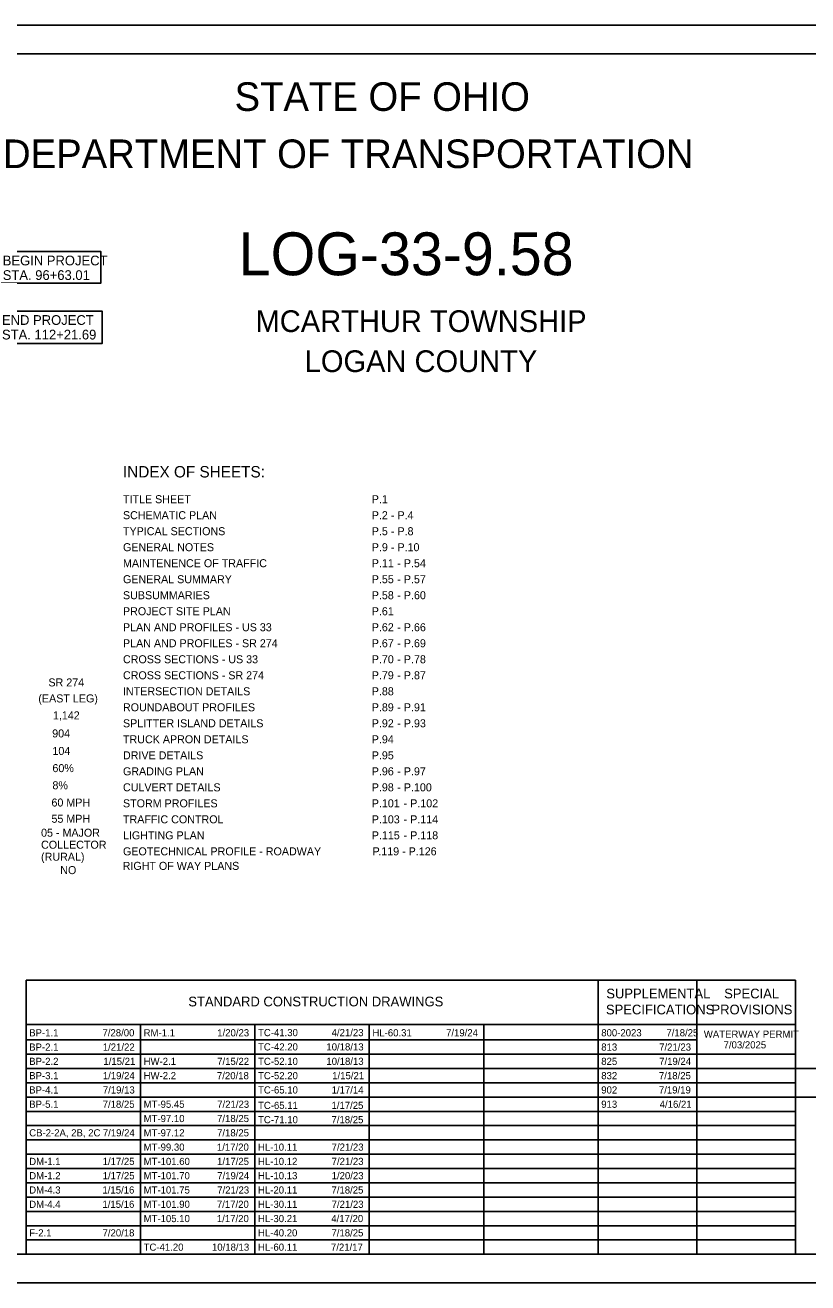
# Model space of a CAD drawing. Extents: x -5.9 to 34, y 0 to 22.
# Drawn here: x 10.13 to 23.82, y 0 to 22 of the extents above; entities that cross this region are included whole.
import ezdxf

# ---------------------------------------------------------------- set-up
doc = ezdxf.new("R2010")
doc.units = 0
for name, color, linetype in [('SH_Border', 7, 'Continuous'), ('SH_Cut_Line', 7, 'Continuous'), ('SH_Data', 7, 'Continuous'), ('SH_Text', 7, 'Continuous')]:
    doc.layers.add(name, color=color, linetype=linetype)

msp = doc.modelspace()

# ---------------------------------------------------------------- linework, layer by layer
at = {"layer": 'SH_Border'}
msp.add_lwpolyline([(1.5, 21.5), (33.5, 21.5), (33.5, 0.5), (1.5, 0.5)], close=True, dxfattribs=at)
at = {"layer": 'SH_Cut_Line'}
msp.add_lwpolyline([(0, 0), (34, 0), (34, 22), (0, 22)], close=True, dxfattribs=at)
at = {"layer": 'SH_Data'}
for p, q in [((10.15, 5.292), (23.6, 5.292)), ((10.15, 0.5), (10.15, 5.292)), ((20.15, 0.5), (20.15, 5.292)), ((21.875, 0.5), (21.875, 5.292)), ((23.6, 0.5), (23.6, 5.292)), ((10.15, 4.521), (23.6, 4.521)), ((12.15, 0.5), (12.15, 4.521)), ((14.15, 0.5), (14.15, 4.521)), ((16.15, 0.5), (16.15, 4.521)), ((18.15, 0.5), (18.15, 4.521)), ((10.15, 4.25), (21.875, 4.25)), ((10.15, 4), (23.6, 4)), ((10.15, 3.75), (23.6, 3.75)), ((23.6, 3.75), (26.4, 3.75)), ((23.6, 0.5), (23.6, 3.75)), ((10.15, 3.5), (23.6, 3.5)), ((10.15, 3.25), (23.6, 3.25)), ((23.6, 3.25), (26.4, 3.25)), ((10.15, 3), (23.6, 3)), ((10.15, 2.75), (23.6, 2.75)), ((10.15, 2.5), (23.6, 2.5)), ((10.15, 2.25), (23.6, 2.25)), ((10.15, 2), (23.6, 2)), ((10.15, 1.75), (23.6, 1.75)), ((10.15, 1.5), (23.6, 1.5)), ((10.15, 1.25), (23.6, 1.25)), ((10.15, 1), (23.6, 1)), ((10.15, 0.75), (23.6, 0.75))]:
    msp.add_line(p, q, dxfattribs=at)
at = {"layer": 'SH_Text'}
for points in [[(9.672, 17.488), (11.459, 17.488), (11.459, 18.038), (9.672, 18.038)], [(9.659, 16.431), (11.478, 16.431), (11.478, 16.997), (9.659, 16.997)]]:
    msp.add_lwpolyline(points, close=True, dxfattribs=at)

# ---------------------------------------------------------------- texts
for s, height, p in [('STATE OF OHIO', 0.5, (13.795, 20.5)), ('DEPARTMENT OF TRANSPORTATION', 0.5, (9.747, 19.5)), ('LOG-33-9.58', 0.75, (13.868, 17.625)), ('BEGIN PROJECT', 0.17, (9.742, 17.798)), ('STA. 96+63.01', 0.17, (9.742, 17.543)), ('MCARTHUR TOWNSHIP', 0.38, (14.162, 16.632)), ('END PROJECT', 0.17, (9.729, 16.757)), ('STA. 112+21.69', 0.17, (9.729, 16.502)), ('LOGAN COUNTY', 0.38, (15.021, 15.932)), ('INDEX OF SHEETS:', 0.2, (11.844, 14.088)), ('TITLE SHEET', 0.14, (11.844, 13.638)), ('P.1', 0.14, (16.193, 13.638)), ('SCHEMATIC PLAN', 0.14, (11.844, 13.358)), ('P.2', 0.14, (16.193, 13.358)), ('P.4', 0.14, (16.642, 13.358)), ('TYPICAL SECTIONS', 0.14, (11.844, 13.078)), ('P.5', 0.14, (16.193, 13.078)), (' - ', 0.14, (16.475, 13.358)), ('P.8', 0.14, (16.642, 13.078)), (' - ', 0.14, (16.475, 13.078)), ('GENERAL NOTES', 0.14, (11.844, 12.798)), ('P.9', 0.14, (16.193, 12.798)), (' - ', 0.14, (16.475, 12.798)), ('P.10', 0.14, (16.642, 12.798)), ('MAINTENENCE OF TRAFFIC', 0.14, (11.844, 12.518)), ('P.11', 0.14, (16.193, 12.518)), (' - ', 0.14, (16.586, 12.518)), ('P.54', 0.14, (16.754, 12.518)), ('GENERAL SUMMARY', 0.14, (11.844, 12.238)), ('P.55', 0.14, (16.193, 12.238)), ('P.57', 0.14, (16.754, 12.238)), (' - ', 0.14, (16.586, 12.238)), ('SUBSUMMARIES', 0.14, (11.844, 11.958)), ('P.58', 0.14, (16.193, 11.958)), (' - ', 0.14, (16.586, 11.958)), ('P.60', 0.14, (16.754, 11.958)), ('PROJECT SITE PLAN', 0.14, (11.844, 11.678)), ('P.61', 0.14, (16.193, 11.678)), ('PLAN AND PROFILES - US 33', 0.14, (11.844, 11.398)), ('P.62', 0.14, (16.193, 11.398)), (' - ', 0.14, (16.586, 11.398)), ('P.66', 0.14, (16.754, 11.398)), ('PLAN AND PROFILES - SR 274', 0.14, (11.844, 11.118)), ('P.67', 0.14, (16.193, 11.118)), ('P.69', 0.14, (16.754, 11.118)), (' - ', 0.14, (16.586, 11.118)), ('CROSS SECTIONS - US 33', 0.14, (11.844, 10.838)), ('P.70', 0.14, (16.193, 10.838)), (' - ', 0.14, (16.586, 10.838)), ('P.78', 0.14, (16.754, 10.838)), ('SR 274', 0.14, (10.541, 10.433)), ('CROSS SECTIONS - SR 274', 0.14, (11.844, 10.558)), ('P.79', 0.14, (16.193, 10.558)), (' - ', 0.14, (16.586, 10.558)), ('P.87', 0.14, (16.754, 10.558)), ('INTERSECTION DETAILS', 0.14, (11.844, 10.278)), ('P.88', 0.14, (16.193, 10.278)), ('(EAST LEG)', 0.14, (10.365, 10.153)), ('ROUNDABOUT PROFILES', 0.14, (11.844, 9.998)), ('P.89', 0.14, (16.193, 9.998)), ('P.91', 0.14, (16.754, 9.998)), ('1,142', 0.14, (10.619, 9.856)), (' - ', 0.14, (16.586, 9.998)), ('904', 0.14, (10.607, 9.541)), ('SPLITTER ISLAND DETAILS ', 0.14, (11.844, 9.718)), ('P.92', 0.14, (16.193, 9.718)), (' - ', 0.14, (16.586, 9.718)), ('P.93', 0.14, (16.754, 9.718)), ('TRUCK APRON DETAILS', 0.14, (11.844, 9.438)), ('P.94', 0.14, (16.193, 9.438)), ('104', 0.14, (10.611, 9.234)), ('DRIVE DETAILS', 0.14, (11.844, 9.158)), ('P.95', 0.14, (16.193, 9.158)), ('60%', 0.14, (10.611, 8.934)), ('GRADING PLAN', 0.14, (11.844, 8.878)), ('P.96', 0.14, (16.193, 8.878)), (' - ', 0.14, (16.586, 8.878)), ('P.97', 0.14, (16.754, 8.878)), ('8%', 0.14, (10.611, 8.634)), ('CULVERT DETAILS', 0.14, (11.844, 8.598)), ('P.98', 0.14, (16.193, 8.598)), (' - ', 0.14, (16.586, 8.598)), ('P.100', 0.14, (16.754, 8.598)), ('60 MPH', 0.14, (10.594, 8.332)), ('STORM PROFILES', 0.14, (11.844, 8.318)), ('P.101', 0.14, (16.193, 8.318)), (' - ', 0.14, (16.698, 8.318)), ('P.102', 0.14, (16.865, 8.318)), ('55 MPH', 0.14, (10.594, 8.048)), ('TRAFFIC CONTROL', 0.14, (11.844, 8.038)), ('P.103', 0.14, (16.193, 8.038)), ('P.114', 0.14, (16.865, 8.038)), ('05 - MAJOR ', 0.14, (10.412, 7.804)), (' - ', 0.14, (16.698, 8.038)), ('COLLECTOR ', 0.14, (10.412, 7.594)), ('LIGHTING PLAN', 0.14, (11.844, 7.758)), ('P.115', 0.14, (16.193, 7.758)), (' - ', 0.14, (16.698, 7.758)), ('P.118', 0.14, (16.865, 7.758)), ('(RURAL)', 0.14, (10.412, 7.384)), ('GEOTECHNICAL PROFILE - ROADWAY', 0.14, (11.844, 7.478)), ('       P', 0.14, (15.844, 7.478)), ('.119 - P.126', 0.14, (16.307, 7.478)), ('NO', 0.14, (10.748, 7.15)), ('RIGHT OF WAY PLANS', 0.14, (11.838, 7.224)), ('SUPPLEMENTAL', 0.17, (20.293, 4.976)), ('SPECIAL', 0.17, (22.354, 4.976)), ('STANDARD CONSTRUCTION DRAWINGS', 0.17, (12.986, 4.836)), ('SPECIFICATIONS', 0.17, (20.287, 4.696)), ('PROVISIONS', 0.17, (22.132, 4.696)), ('BP-1.1', 0.125, (10.205, 4.312)), ('7/28/00', 0.125, (11.486, 4.312)), ('RM-1.1', 0.125, (12.205, 4.312)), ('1/20/23', 0.125, (13.492, 4.312)), ('TC-41.30', 0.125, (14.205, 4.315)), ('4/21/23', 0.125, (15.492, 4.315)), ('HL-60.31', 0.125, (16.205, 4.312)), ('7/19/24', 0.125, (17.492, 4.312)), ('800-2023', 0.125, (20.205, 4.312)), ('7/18/25', 0.125, (21.344, 4.312)), ('WATERWAY PERMIT', 0.125, (21.998, 4.288)), ('BP-2.1', 0.125, (10.205, 4.062)), ('1/21/22', 0.125, (11.491, 4.062)), ('TC-42.20', 0.125, (14.205, 4.065)), ('10/18/13', 0.125, (15.4, 4.065)), ('813', 0.125, (20.205, 4.062)), ('7/21/23', 0.125, (21.217, 4.062)), ('7/03/2025', 0.125, (22.344, 4.101)), ('BP-2.2', 0.125, (10.205, 3.812)), ('1/15/21', 0.125, (11.502, 3.812)), ('HW-2.1', 0.125, (12.205, 3.812)), ('7/15/22', 0.125, (13.491, 3.812)), ('TC-52.10', 0.125, (14.205, 3.812)), ('10/18/13', 0.125, (15.4, 3.812)), ('825', 0.125, (20.205, 3.812)), ('7/19/24', 0.125, (21.217, 3.812)), ('BP-3.1', 0.125, (10.205, 3.562)), ('1/19/24', 0.125, (11.492, 3.562)), ('HW-2.2', 0.125, (12.205, 3.562)), ('7/20/18', 0.125, (13.487, 3.562)), ('TC-52.20', 0.125, (14.205, 3.562)), ('1/15/21', 0.125, (15.502, 3.562)), ('832', 0.125, (20.205, 3.562)), ('7/18/25', 0.125, (21.214, 3.562)), ('BP-4.1', 0.125, (10.205, 3.312)), ('7/19/13', 0.125, (11.492, 3.312)), ('TC-65.10', 0.125, (14.205, 3.312)), ('1/17/14', 0.125, (15.492, 3.312)), ('902', 0.125, (20.205, 3.312)), ('7/19/19', 0.125, (21.213, 3.312)), ('BP-5.1', 0.125, (10.205, 3.062)), ('7/18/25', 0.125, (11.489, 3.062)), ('MT-95.45', 0.125, (12.205, 3.062)), ('7/21/23', 0.125, (13.492, 3.062)), ('TC-65.11', 0.125, (14.205, 3.042)), ('1/17/25', 0.125, (15.489, 3.042)), ('913', 0.125, (20.205, 3.062)), ('4/16/21', 0.125, (21.227, 3.062)), ('MT-97.10', 0.125, (12.205, 2.812)), ('7/18/25', 0.125, (13.489, 2.812)), ('TC-71.10', 0.125, (14.205, 2.792)), ('7/18/25', 0.125, (15.489, 2.792)), ('CB-2-2A, 2B, 2C', 0.125, (10.205, 2.562)), ('7/19/24', 0.125, (11.492, 2.562)), ('MT-97.12', 0.125, (12.205, 2.562)), ('7/18/25', 0.125, (13.489, 2.562)), ('MT-99.30', 0.125, (12.205, 2.312)), ('1/17/20', 0.125, (13.486, 2.312)), ('HL-10.11', 0.125, (14.205, 2.312)), ('7/21/23', 0.125, (15.492, 2.312)), ('DM-1.1', 0.125, (10.205, 2.062)), ('1/17/25', 0.125, (11.489, 2.062)), ('MT-101.60', 0.125, (12.205, 2.062)), ('1/17/25', 0.125, (13.489, 2.062)), ('HL-10.12', 0.125, (14.205, 2.062)), ('7/21/23', 0.125, (15.492, 2.062)), ('DM-1.2', 0.125, (10.205, 1.812)), ('1/17/25', 0.125, (11.489, 1.812)), ('MT-101.70', 0.125, (12.205, 1.812)), ('7/19/24', 0.125, (13.492, 1.812)), ('HL-10.13', 0.125, (14.205, 1.812)), ('1/20/23', 0.125, (15.492, 1.812)), ('DM-4.3', 0.125, (10.205, 1.562)), ('1/15/16', 0.125, (11.485, 1.562)), ('MT-101.75', 0.125, (12.205, 1.562)), ('7/21/23', 0.125, (13.492, 1.562)), ('HL-20.11', 0.125, (14.205, 1.562)), ('7/18/25', 0.125, (15.489, 1.562)), ('DM-4.4', 0.125, (10.205, 1.312)), ('1/15/16', 0.125, (11.485, 1.312)), ('MT-101.90', 0.125, (12.205, 1.312)), ('7/17/20', 0.125, (13.486, 1.312)), ('HL-30.11', 0.125, (14.205, 1.312)), ('7/21/23', 0.125, (15.492, 1.312)), ('MT-105.10', 0.125, (12.205, 1.062)), ('1/17/20', 0.125, (13.486, 1.062)), ('HL-30.21', 0.125, (14.205, 1.062)), ('4/17/20', 0.125, (15.486, 1.062)), ('F-2.1', 0.125, (10.205, 0.812)), ('7/20/18', 0.125, (11.487, 0.812)), ('HL-40.20', 0.125, (14.205, 0.812)), ('7/18/25', 0.125, (15.489, 0.812)), ('TC-41.20', 0.125, (12.205, 0.562)), ('10/18/13', 0.125, (13.4, 0.562)), ('HL-60.11', 0.125, (14.205, 0.562)), ('7/21/17', 0.125, (15.48, 0.562))]:
    msp.add_text(s, height=height, dxfattribs=at).set_placement(p)

doc.saveas('drawing.dxf')
